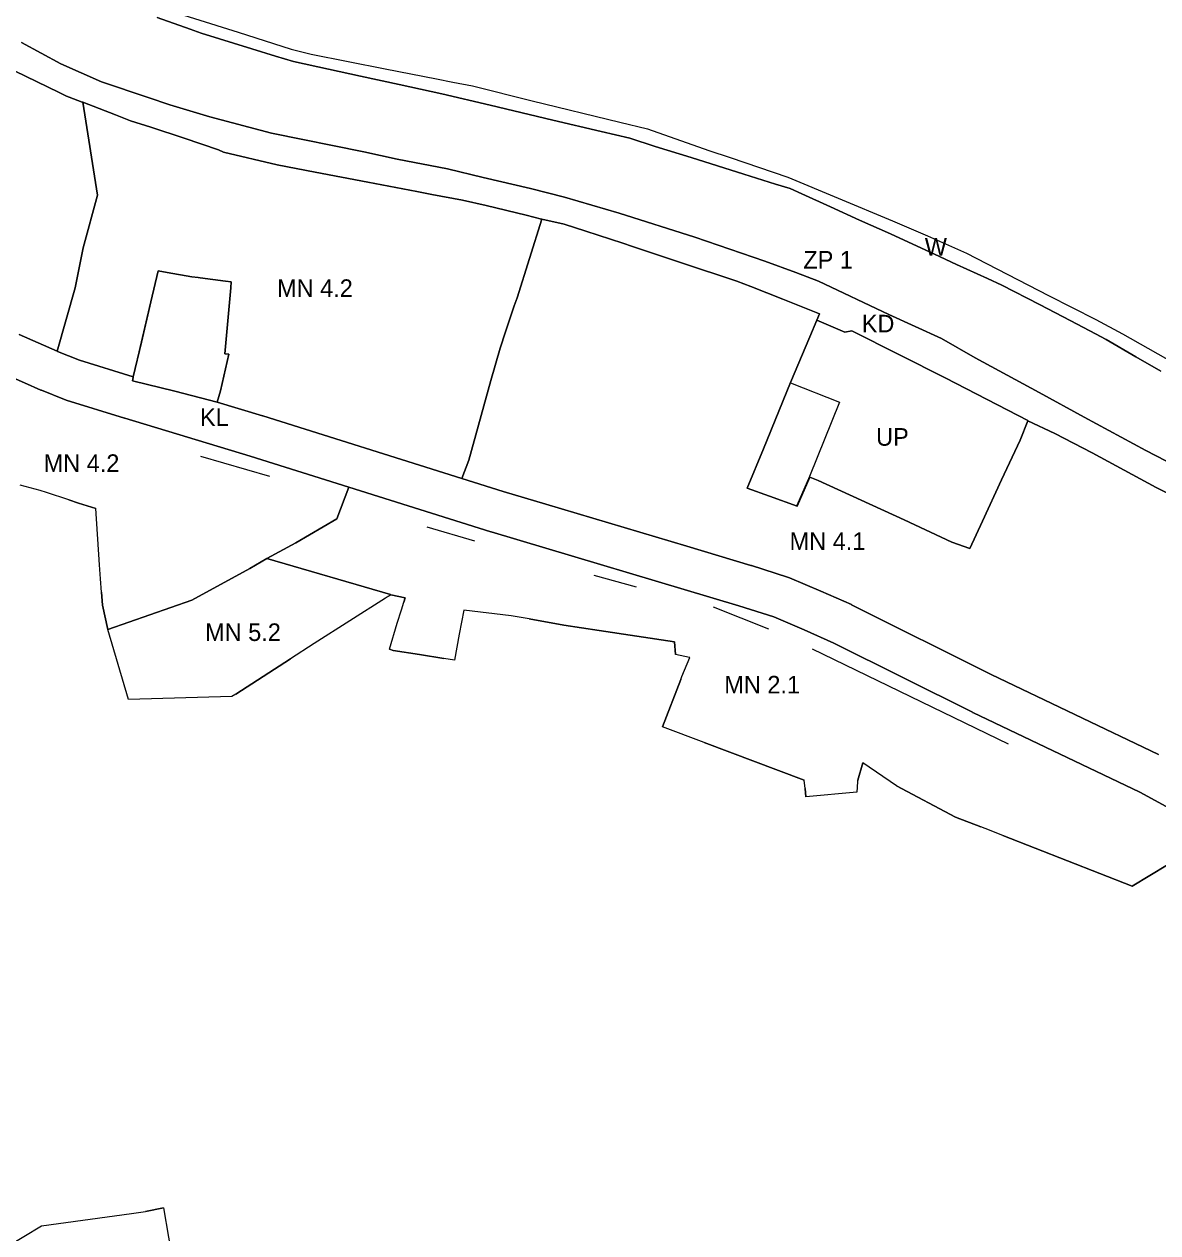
# Model space of a CAD drawing. Extents: x 7421359 to 7422386, y 5546414 to 5547388.
# Drawn here: x 7421829.1 to 7422151.6, y 5546861.7 to 5547205.6 of the extents above; entities that cross this region are included whole.
import ezdxf

# ---------------------------------------------------------------- set-up
doc = ezdxf.new("R2010")
doc.units = 0
for name, color, linetype in [('_ZWIERZTNIEC_KS_JÓZEFA', 7, 'Continuous'), ('linie_rozgraniczajace', 7, 'Continuous'), ('linie_zabudowy', 7, 'Continuous'), ('oznaczenia_przeznaczen', 7, 'Continuous')]:
    doc.layers.add(name, color=color, linetype=linetype)

msp = doc.modelspace()

# ---------------------------------------------------------------- linework, layer by layer
at = {"layer": '_ZWIERZTNIEC_KS_JÓZEFA'}
msp.add_lwpolyline([(7421867.17, 5547135.45), (7421869.82, 5547134.97), (7421876.76, 5547133.72), (7421878.56, 5547133.51), (7421879.14, 5547133.43), (7421886.37, 5547132.5), (7421888, 5547132.3), (7421886.149232, 5547111.852477), (7421887.282398, 5547111.691403), (7421884.91, 5547101.34), (7421883.99, 5547098.08), (7421871.94, 5547101.16), (7421859.89, 5547104.13), (7421860.08, 5547105.12), (7421865.12, 5547126.66)], close=True, dxfattribs=at)
at = {"layer": 'linie_rozgraniczajace'}
for points in [[(7421865.14, 5547211.11), (7421890.02, 5547203.32), (7421905.04, 5547198.5), (7421910.79, 5547197.14), (7421931.82, 5547192.9), (7421946.44, 5547190.07), (7421951.03, 5547189.18), (7421956.64, 5547188.08), (7421973.62, 5547183.87), (7421998.56, 5547177.8), (7422006.45, 5547175.87), (7422023.91, 5547169.7), (7422029.95, 5547167.69), (7422046.4, 5547162.07), (7422060.67, 5547156.16), (7422076.16, 5547149.64), (7422086.13, 5547145.41), (7422097.25, 5547140.5), (7422120.51, 5547128.47), (7422134.03, 5547121.6), (7422141.61, 5547117.54), (7422158.89, 5547107.72)], [(7421866.95, 5547207.56), (7421876.31, 5547204.23), (7421879.48, 5547203.13), (7421893.84, 5547198.67), (7421900.6, 5547196.58), (7421905.74, 5547195), (7421915.65, 5547192.85), (7421924.81, 5547190.86), (7421935.77, 5547188.5), (7421947.97, 5547185.8), (7421961.64, 5547182.6), (7421979.55, 5547178.37), (7421993.22, 5547175.13), (7422001.38, 5547173.21), (7422008.66, 5547170.87), (7422018.84, 5547167.66), (7422033.84, 5547162.97), (7422042.9, 5547160.14), (7422047.05, 5547158.85), (7422050.31, 5547157.4), (7422058.47, 5547153.66), (7422066.74, 5547149.91), (7422075.59, 5547145.94), (7422088.1, 5547140.24), (7422094.4, 5547137.28), (7422103.14, 5547133.23), (7422107.25, 5547131.4), (7422117.96, 5547125.88), (7422126.86, 5547121.24), (7422133.92, 5547117.54), (7422136.98, 5547115.88), (7422145.42, 5547110.99), (7422152.45, 5547106.92)], [(7422152.45, 5547106.92), (7422145.42, 5547110.99), (7422136.98, 5547115.88), (7422133.92, 5547117.54), (7422126.86, 5547121.24), (7422117.96, 5547125.88), (7422107.25, 5547131.4), (7422103.14, 5547133.23), (7422094.4, 5547137.28), (7422088.1, 5547140.24), (7422075.59, 5547145.94), (7422066.74, 5547149.91), (7422058.47, 5547153.66), (7422050.31, 5547157.4), (7422047.05, 5547158.85), (7422042.9, 5547160.14), (7422033.84, 5547162.97), (7422018.84, 5547167.66), (7422008.66, 5547170.87), (7422001.38, 5547173.21), (7421993.22, 5547175.13), (7421979.55, 5547178.37), (7421961.64, 5547182.6), (7421947.97, 5547185.8), (7421935.77, 5547188.5), (7421924.81, 5547190.86), (7421915.65, 5547192.85), (7421905.74, 5547195), (7421900.6, 5547196.58), (7421893.84, 5547198.67), (7421879.48, 5547203.13), (7421876.31, 5547204.23), (7421866.95, 5547207.56)], [(7421828.31, 5547200.38), (7421839.52, 5547194.4), (7421851.05, 5547189.27), (7421864.39, 5547184.81), (7421870.56, 5547182.67), (7421881.89, 5547179.32), (7421899.48, 5547174.67), (7421925.73, 5547169.3), (7421935.23, 5547167.19), (7421949.52, 5547164.43), (7421959.69, 5547161.98), (7421973.16, 5547158.84), (7421982.8, 5547156.37), (7421998.35, 5547151.88), (7422019.9, 5547145.01), (7422039.84, 5547138.19), (7422048.66, 5547134.97), (7422055.14, 5547132.49), (7422075.06, 5547123.06), (7422090.12, 5547116.16), (7422099.63, 5547110.71), (7422117.85, 5547100.84), (7422130.64, 5547093.85), (7422148.25, 5547084.32), (7422162.37, 5547077.03)], [(7422162.37, 5547077.03), (7422148.25, 5547084.32), (7422130.64, 5547093.85), (7422117.85, 5547100.84), (7422099.63, 5547110.71), (7422090.12, 5547116.16), (7422075.06, 5547123.06), (7422055.14, 5547132.49), (7422048.66, 5547134.97), (7422039.84, 5547138.19), (7422019.9, 5547145.01), (7421998.35, 5547151.88), (7421982.8, 5547156.37), (7421973.16, 5547158.84), (7421959.69, 5547161.98), (7421949.52, 5547164.43), (7421935.23, 5547167.19), (7421925.73, 5547169.3), (7421899.48, 5547174.67), (7421881.89, 5547179.32), (7421870.56, 5547182.67), (7421864.39, 5547184.81), (7421851.05, 5547189.27), (7421839.52, 5547194.4), (7421828.31, 5547200.38)], [(7422151.13, 5547073.79), (7422132.92, 5547083.65), (7422122.31, 5547089.17), (7422114.7, 5547092.79), (7422114.61, 5547092.83), (7422091.35, 5547104.86), (7422064.59, 5547118.34), (7422062.62, 5547118), (7422054.62, 5547121.38), (7422055.4, 5547123.21), (7422044.96, 5547127.34), (7422035.86, 5547130.95), (7422031.88, 5547132.48), (7422016.1, 5547137.77), (7422002.14, 5547142.39), (7421999.41, 5547143.35), (7421988.89, 5547146.74), (7421982.77, 5547148.71), (7421976.34, 5547150.19), (7421976.3, 5547150.2), (7421971.92, 5547151.29), (7421960.58, 5547154.01), (7421953.84, 5547155.54), (7421945.04, 5547157.14), (7421940.77, 5547158.02), (7421926.89, 5547160.64), (7421911.84, 5547163.52), (7421901.11, 5547165.58), (7421885.82, 5547169.19), (7421884.42, 5547169.88), (7421874.64, 5547173.19), (7421865.14, 5547176.35), (7421859.35, 5547178.13), (7421855.06, 5547179.8), (7421845.79, 5547183.4), (7421845.75, 5547183.42), (7421845.62, 5547183.47), (7421841.9, 5547184.85), (7421841.17, 5547185.12), (7421839.01, 5547186.2), (7421826.36, 5547192.36)], [(7421826.36, 5547192.36), (7421839.01, 5547186.2), (7421841.17, 5547185.12), (7421841.9, 5547184.85), (7421845.62, 5547183.47), (7421845.75, 5547183.42), (7421850, 5547157.02), (7421845.92, 5547142.02), (7421843.62, 5547130.61), (7421838.44, 5547112.62), (7421827.63, 5547117.37)], [(7422151.8, 5546997.83), (7422104.2, 5547020.58), (7422064.71, 5547040.34), (7422064.48, 5547040.44), (7422064.44, 5547040.47), (7422055.77, 5547044.27), (7422055.75, 5547044.28), (7422055.72, 5547044.3), (7422046.84, 5547048.09), (7422046.57, 5547048.14), (7422046.32, 5547048.28), (7422036.01, 5547051.6), (7422035.94, 5547051.61), (7422035.89, 5547051.64), (7422017.65, 5547057.08), (7421977.56, 5547069.02), (7421965.41, 5547072.65), (7421953.62, 5547076.35), (7421955.57, 5547081.58), (7421961.9, 5547104.21), (7421964.49, 5547113.42), (7421966.06, 5547118.05), (7421968.51, 5547125.46), (7421969.37, 5547127.72), (7421976.34, 5547150.19), (7421982.77, 5547148.71), (7421988.89, 5547146.74), (7421999.41, 5547143.35), (7422002.14, 5547142.39), (7422016.1, 5547137.77), (7422031.88, 5547132.48), (7422035.86, 5547130.95), (7422044.96, 5547127.34), (7422055.4, 5547123.21), (7422054.62, 5547121.38), (7422052.59, 5547116.64), (7422047.14, 5547103.65), (7422039.41, 5547084.8), (7422034.79, 5547073.64), (7422041.19, 5547071.37), (7422049.04, 5547068.51), (7422052.63, 5547076.71), (7422052.65, 5547076.76), (7422055.04, 5547075.77), (7422079.43, 5547064.58), (7422093.03, 5547058.25), (7422098.14, 5547056.39), (7422101.74, 5547064.17), (7422107.2, 5547075.93), (7422112.46, 5547087.27), (7422114.7, 5547092.79), (7422122.31, 5547089.17), (7422132.92, 5547083.65), (7422151.13, 5547073.79), (7422160.59, 5547069.15)], [(7421796.53, 5547117.93), (7421829.18, 5547103.58), (7421833.87, 5547101.52), (7421833.95, 5547101.5), (7421834.04, 5547101.45), (7421840.59, 5547098.81), (7421840.84, 5547098.76), (7421841.06, 5547098.64), (7421857.67, 5547093.5), (7421857.69, 5547093.49), (7421857.71, 5547093.49), (7421893.42, 5547082.69), (7421921.42, 5547073.89), (7421918.02, 5547064.87), (7421906.36, 5547058.03), (7421898.17, 5547053.58), (7421893.33, 5547050.72), (7421876.76, 5547041.73), (7421852.86, 5547033.41), (7421851.41, 5547040.29), (7421851.09, 5547043.97), (7421850.77, 5547047.76), (7421850.55, 5547051.83), (7421849.52, 5547067.79), (7421849.52, 5547067.79), (7421849.52, 5547067.79), (7421844.54, 5547069.37), (7421841.8, 5547070.27), (7421835.44, 5547072.38), (7421833.69, 5547072.95), (7421827.94, 5547074.48)], [(7422153.98, 5546982.99), (7422146.48, 5546987.07), (7422098.97, 5547009.78), (7422098.95, 5547009.79), (7422098.88, 5547009.83), (7422059.48, 5547029.54), (7422050.98, 5547033.27), (7422042.38, 5547036.95), (7422032.4, 5547040.16), (7421961.94, 5547061.16), (7421961.9, 5547061.18), (7421961.85, 5547061.19), (7421921.42, 5547073.89), (7421893.42, 5547082.69), (7421857.71, 5547093.49), (7421857.69, 5547093.49), (7421857.67, 5547093.5), (7421841.06, 5547098.64), (7421840.84, 5547098.76), (7421840.59, 5547098.81), (7421834.04, 5547101.45), (7421833.95, 5547101.5), (7421833.87, 5547101.52), (7421829.18, 5547103.58), (7421796.53, 5547117.93)], [(7421827.63, 5547117.37), (7421838.44, 5547112.62), (7421838.51, 5547112.59), (7421838.62, 5547112.54), (7421844.84, 5547110.03), (7421860.121298, 5547105.2965), (7421860.08, 5547105.12), (7421859.89, 5547104.13), (7421871.94, 5547101.16), (7421883.99, 5547098.08), (7421896.92, 5547094.17), (7421896.95, 5547094.16), (7421896.98, 5547094.15), (7421953.62, 5547076.35), (7421965.41, 5547072.65), (7421977.56, 5547069.02), (7422017.65, 5547057.08), (7422035.89, 5547051.64), (7422035.94, 5547051.61), (7422036.01, 5547051.6), (7422046.32, 5547048.28), (7422046.57, 5547048.14), (7422046.84, 5547048.09), (7422055.72, 5547044.3), (7422055.75, 5547044.28), (7422055.77, 5547044.27), (7422064.44, 5547040.47), (7422064.48, 5547040.44), (7422064.71, 5547040.34), (7422104.2, 5547020.58), (7422151.8, 5546997.83)], [(7422159.45, 5546969.45), (7422144.36, 5546960.37), (7422107.57, 5546974.79), (7422102.49, 5546976.78), (7422102.49, 5546976.78), (7422101.25, 5546977.25), (7422094.05, 5546979.99), (7422077.27, 5546988.94), (7422077.27, 5546988.94), (7422067.67, 5546995.47), (7422067.67, 5546995.47), (7422066.26, 5546990.51), (7422066.17, 5546990.19), (7422066.17, 5546990.19), (7422066.16, 5546990.01), (7422065.98, 5546987.12), (7422051.52, 5546985.79), (7422051.27, 5546988.16), (7422051.01, 5546990.53), (7422051.01, 5546990.53), (7422051.01, 5546990.53), (7422022.6, 5547001.22), (7422010.73, 5547005.69), (7422015.9, 5547019.13), (7422015.9, 5547019.13), (7422016.24, 5547019.97), (7422018.44, 5547025.37), (7422018.44, 5547025.37), (7422018.44, 5547025.37), (7422018.43, 5547025.37), (7422014.37, 5547026.28), (7422014.37, 5547026.28), (7422014.12, 5547029.86), (7422014.12, 5547029.86), (7421992.7, 5547033.12), (7421982.68, 5547034.62), (7421972.82, 5547036.39), (7421972.82, 5547036.39), (7421967.7, 5547037.24), (7421954.14, 5547038.9), (7421952.9, 5547032.08), (7421952.89, 5547032.06), (7421951.54, 5547024.62), (7421948.48, 5547025.13), (7421941.55, 5547026.29), (7421934.1, 5547027.4), (7421933, 5547027.75), (7421935.17, 5547035.15), (7421936.43, 5547038.94), (7421937.12, 5547041.16), (7421937.49, 5547042.38), (7421933.38, 5547043.29), (7421933.29, 5547043.31), (7421898.17, 5547053.58), (7421906.36, 5547058.03), (7421918.02, 5547064.87), (7421921.42, 5547073.89), (7421961.85, 5547061.19), (7421961.9, 5547061.18), (7421961.94, 5547061.16), (7422032.4, 5547040.16), (7422042.38, 5547036.95), (7422050.98, 5547033.27), (7422059.48, 5547029.54), (7422098.88, 5547009.83), (7422098.95, 5547009.79), (7422098.97, 5547009.78), (7422146.48, 5546987.07), (7422153.98, 5546982.99)], [(7422160.59, 5547069.15), (7422151.13, 5547073.79)], [(7421823.97, 5546857.6), (7421834.05, 5546863.7), (7421859.65, 5546867.22), (7421863.64, 5546867.76), (7421863.64, 5546867.76), (7421868.77, 5546868.77), (7421872.97, 5546843.81)]]:
    msp.add_lwpolyline(points, dxfattribs=at)
for points in [[(7421845.75, 5547183.42), (7421845.79, 5547183.4), (7421855.06, 5547179.8), (7421859.35, 5547178.13), (7421865.14, 5547176.35), (7421874.64, 5547173.19), (7421884.42, 5547169.88), (7421885.82, 5547169.19), (7421901.11, 5547165.58), (7421911.84, 5547163.52), (7421926.89, 5547160.64), (7421940.77, 5547158.02), (7421945.04, 5547157.14), (7421953.84, 5547155.54), (7421960.58, 5547154.01), (7421971.92, 5547151.29), (7421976.3, 5547150.2), (7421976.34, 5547150.19), (7421969.37, 5547127.72), (7421968.51, 5547125.46), (7421966.06, 5547118.05), (7421964.49, 5547113.42), (7421961.9, 5547104.21), (7421955.57, 5547081.58), (7421953.62, 5547076.35), (7421896.98, 5547094.15), (7421896.95, 5547094.16), (7421896.92, 5547094.17), (7421883.99, 5547098.08), (7421884.91, 5547101.34), (7421887.282398, 5547111.691403), (7421886.149232, 5547111.852477), (7421887.87, 5547130.59), (7421888, 5547132.3), (7421886.37, 5547132.5), (7421879.14, 5547133.43), (7421878.56, 5547133.51), (7421876.76, 5547133.72), (7421869.82, 5547134.97), (7421867.17, 5547135.45), (7421865.12, 5547126.66), (7421862.43, 5547115.17), (7421860.121298, 5547105.2965), (7421844.84, 5547110.03), (7421838.62, 5547112.54), (7421838.51, 5547112.59), (7421838.44, 5547112.62), (7421843.62, 5547130.61), (7421845.92, 5547142.02), (7421850, 5547157.02)], [(7421865.12, 5547126.66), (7421867.17, 5547135.45), (7421869.82, 5547134.97), (7421876.76, 5547133.72), (7421878.56, 5547133.51), (7421879.14, 5547133.43), (7421886.37, 5547132.5), (7421888, 5547132.3), (7421887.87, 5547130.59), (7421886.149232, 5547111.852477), (7421887.282398, 5547111.691403), (7421884.91, 5547101.34), (7421883.99, 5547098.08), (7421871.94, 5547101.16), (7421859.89, 5547104.13), (7421860.08, 5547105.12), (7421860.121298, 5547105.2965), (7421862.43, 5547115.17)], [(7422054.62, 5547121.38), (7422062.62, 5547118), (7422064.59, 5547118.34), (7422091.35, 5547104.86), (7422114.61, 5547092.83), (7422114.7, 5547092.79), (7422112.46, 5547087.27), (7422107.2, 5547075.93), (7422101.74, 5547064.17), (7422098.14, 5547056.39), (7422093.03, 5547058.25), (7422079.43, 5547064.58), (7422055.04, 5547075.77), (7422052.65, 5547076.76), (7422052.63, 5547076.71), (7422049.04, 5547068.51), (7422041.19, 5547071.37), (7422034.79, 5547073.64), (7422039.41, 5547084.8), (7422047.14, 5547103.65), (7422052.59, 5547116.64)], [(7421841.8, 5547070.27), (7421844.54, 5547069.37), (7421849.52, 5547067.79), (7421849.52, 5547067.79), (7421844.54, 5547069.37)], [(7421898.17, 5547053.58), (7421933.29, 5547043.31), (7421933.38, 5547043.29), (7421932.11, 5547042.48), (7421931.86, 5547042.32), (7421911.62, 5547029.42), (7421904.89, 5547025.08), (7421897.07, 5547020.04), (7421889.34, 5547015.02), (7421888.2, 5547014.28), (7421858.74, 5547013.44), (7421852.86, 5547033.4), (7421852.86, 5547033.41), (7421876.76, 5547041.73), (7421893.33, 5547050.72)], [(7421851.09, 5547043.97), (7421851.41, 5547040.29), (7421852.86, 5547033.41), (7421852.86, 5547033.4), (7421852.86, 5547033.4), (7421851.41, 5547040.3)], [(7421933.38, 5547043.29), (7421937.49, 5547042.38), (7421937.12, 5547041.16), (7421937.49, 5547042.38), (7421933.39, 5547043.29), (7421932.11, 5547042.48)], [(7421972.82, 5547036.39), (7421982.68, 5547034.62), (7421992.7, 5547033.12), (7422014.12, 5547029.86), (7421992.7, 5547033.12), (7421982.68, 5547034.62)], [(7422014.12, 5547029.86), (7422014.12, 5547029.86), (7422014.37, 5547026.28)], [(7421933, 5547027.75), (7421934.1, 5547027.4), (7421941.55, 5547026.29), (7421948.48, 5547025.13), (7421941.55, 5547026.29), (7421934.1, 5547027.4), (7421933, 5547027.75)], [(7421904.89, 5547025.08), (7421897.07, 5547020.04), (7421889.34, 5547015.02), (7421897.07, 5547020.04)], [(7422018.43, 5547025.37), (7422018.44, 5547025.37), (7422018.44, 5547025.37)], [(7422015.9, 5547019.13), (7422010.73, 5547005.69), (7422010.73, 5547005.69)], [(7422022.6, 5547001.22), (7422051.01, 5546990.53), (7422051.01, 5546990.53)], [(7422067.67, 5546995.47), (7422067.67, 5546995.47), (7422066.26, 5546990.51)], [(7422051.27, 5546988.16), (7422051.52, 5546985.79), (7422051.52, 5546985.79)], [(7422077.27, 5546988.94), (7422094.05, 5546979.99), (7422101.25, 5546977.25), (7422094.05, 5546979.99)], [(7422107.57, 5546974.79), (7422144.36, 5546960.37), (7422159.45, 5546969.45), (7422162.35, 5546971.73), (7422162.35, 5546971.73), (7422159.45, 5546969.45), (7422144.36, 5546960.37)], [(7421863.64, 5546867.76), (7421868.77, 5546868.77), (7421868.77, 5546868.77)]]:
    msp.add_lwpolyline(points, close=True, dxfattribs=at)
at = {"layer": 'linie_zabudowy'}
for points in [[(7422047.16, 5547103.57), (7422061.09, 5547098.05), (7422052.52, 5547076.89), (7422048.93, 5547068.67)], [(7421899.01, 5547076.93), (7421879.32, 5547082.62)], [(7421943.68, 5547062.59), (7421957.21, 5547058.64)], [(7422003.29, 5547045.42), (7421991.24, 5547048.77)], [(7422025.1, 5547039.82), (7422040.84, 5547033.57)], [(7422053.25, 5547027.85), (7422109.03, 5547000.86)]]:
    msp.add_lwpolyline(points, dxfattribs=at)

# ---------------------------------------------------------------- texts
at = {"layer": 'oznaczenia_przeznaczen'}
for s, p in [('W', (7422085.340741, 5547139.788519)), ('ZP 1', (7422050.779641, 5547136.099642)), ('MN 4.2', (7421901.041328, 5547128.020011)), ('KD', (7422067.400615, 5547117.931235)), ('KL', (7421879.111664, 5547091.282277)), ('UP', (7422071.483196, 5547085.690011)), ('MN 4.2', (7421834.631328, 5547078.220011)), ('MN 4.1', (7422046.877118, 5547056.006433)), ('MN 5.2', (7421880.571328, 5547030.120011)), ('MN 2.1', (7422028.287118, 5547015.190011))]:
    msp.add_text(s, height=4.999998, dxfattribs=at).set_placement(p)

doc.saveas('drawing.dxf')
